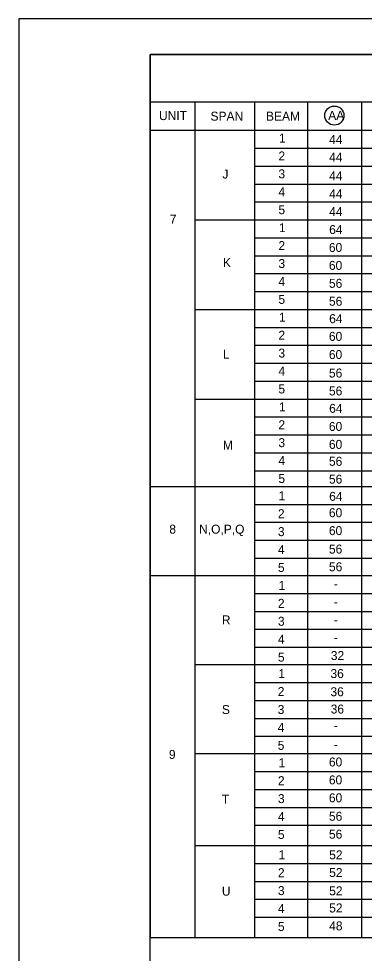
# Model space of a CAD drawing. Extents: x -50.5 to -14.4, y -5.1 to 16.9.
# Drawn here: x -50.52 to -45.7, y 3.9 to 16.93 of the extents above; entities that cross this region are included whole.
import ezdxf

# ---------------------------------------------------------------- set-up
doc = ezdxf.new("R2010")
doc.units = 0
for name, color, linetype in [('BR_AUTO DIMENSION', 7, 'Continuous'), ('BR_BORDER LINES', 7, 'Continuous'), ('BR_TABLE LINES', 7, 'Continuous'), ('BR_TEXT', 7, 'Continuous'), ('Level 31', 7, 'Continuous')]:
    doc.layers.add(name, color=color, linetype=linetype)

msp = doc.modelspace()

# ---------------------------------------------------------------- linework, layer by layer
at = {"layer": 'BR_AUTO DIMENSION'}
msp.add_circle((-46.121, 15.583), 0.133, dxfattribs=at)
at = {"layer": 'BR_BORDER LINES'}
for p, q in [((-48.685, 16.434), (-48.685, 4.12)), ((-48.685, 16.434), (-37.494, 16.434)), ((-15.019, 16.434), (-48.685, 16.434)), ((-48.685, -4.566), (-48.685, 16.434)), ((-48.685, 4.12), (-37.494, 4.12))]:
    msp.add_line(p, q, dxfattribs=at)
at = {"layer": 'BR_TABLE LINES'}
for p, q in [((-48.685, 15.775), (-37.494, 15.775)), ((-48.065, 15.775), (-48.065, 4.12)), ((-47.233, 15.775), (-47.233, 4.12)), ((-46.494, 15.775), (-46.494, 4.12)), ((-46.494, 15.775), (-46.494, 4.12)), ((-45.744, 15.775), (-45.744, 4.12)), ((-48.685, 15.378), (-37.494, 15.378)), ((-47.233, 15.128), (-37.494, 15.128)), ((-47.233, 14.878), (-37.494, 14.878)), ((-47.233, 14.628), (-37.494, 14.628)), ((-47.233, 14.378), (-37.494, 14.378)), ((-48.065, 14.129), (-37.494, 14.129)), ((-47.233, 13.879), (-37.494, 13.879)), ((-47.233, 13.629), (-37.494, 13.629)), ((-47.233, 13.379), (-37.494, 13.379)), ((-47.233, 13.129), (-37.494, 13.129)), ((-48.065, 12.879), (-37.494, 12.879)), ((-47.233, 12.629), (-37.494, 12.629)), ((-47.233, 12.379), (-37.494, 12.379)), ((-47.233, 12.129), (-37.494, 12.129)), ((-47.233, 11.879), (-37.494, 11.879)), ((-48.065, 11.63), (-37.494, 11.63)), ((-47.233, 11.38), (-37.494, 11.38)), ((-47.233, 11.13), (-37.494, 11.13)), ((-47.233, 10.88), (-37.494, 10.88)), ((-47.233, 10.63), (-37.494, 10.63)), ((-48.685, 10.411), (-37.494, 10.411)), ((-47.233, 10.161), (-37.494, 10.161)), ((-47.233, 9.911), (-37.494, 9.911)), ((-47.233, 9.661), (-37.494, 9.661)), ((-47.233, 9.411), (-37.494, 9.411)), ((-48.685, 9.169), (-37.494, 9.169)), ((-47.233, 8.919), (-37.494, 8.919)), ((-47.233, 8.669), (-37.494, 8.669)), ((-47.233, 8.419), (-37.494, 8.419)), ((-47.233, 8.169), (-37.494, 8.169)), ((-48.065, 7.927), (-37.494, 7.927)), ((-47.233, 7.677), (-37.494, 7.677)), ((-47.233, 7.427), (-37.494, 7.427)), ((-47.233, 7.177), (-37.494, 7.177)), ((-47.233, 6.927), (-37.494, 6.927)), ((-48.065, 6.685), (-37.494, 6.685)), ((-47.233, 6.435), (-37.494, 6.435)), ((-47.233, 6.185), (-37.494, 6.185)), ((-47.233, 5.935), (-37.494, 5.935)), ((-47.233, 5.685), (-37.494, 5.685)), ((-48.065, 5.403), (-37.494, 5.403)), ((-47.233, 5.153), (-37.494, 5.153)), ((-47.233, 4.903), (-37.494, 4.903)), ((-47.233, 4.653), (-37.494, 4.653)), ((-47.233, 4.403), (-37.494, 4.403))]:
    msp.add_line(p, q, dxfattribs=at)
at = {"layer": 'Level 31'}
msp.add_lwpolyline([(-50.519, -5.066), (-14.519, -5.066), (-14.519, 16.934), (-50.519, 16.934)], close=True, dxfattribs=at)

# ---------------------------------------------------------------- texts
at = {"layer": 'BR_TEXT'}
for s, p in [('UNIT', (-48.564, 15.52)), ('AA', (-46.206, 15.523)), ('SPAN', (-47.846, 15.512)), ('BEAM', (-47.073, 15.512)), ('J', (-47.68, 14.705)), ('7', (-48.413, 14.076)), ('K', (-47.674, 13.47)), ('L', (-47.674, 12.192)), ('M', (-47.674, 10.922)), ('8', (-48.42, 9.753)), ('N,O,P,Q', (-48.005, 9.752)), ('R', (-47.688, 8.487)), ('S', (-47.688, 7.237)), ('9', (-48.426, 6.611)), ('T', (-47.688, 5.987)), ('U', (-47.688, 4.704))]:
    msp.add_text(s, height=0.125, rotation=360, dxfattribs=at).set_placement(p)
for s, p in [('1', (-46.892, 15.207)), ('44', (-46.193, 15.188)), ('2', (-46.9, 14.957)), ('44', (-46.193, 14.941)), ('3', (-46.9, 14.707)), ('44', (-46.193, 14.68)), ('4', (-46.9, 14.457)), ('44', (-46.193, 14.43)), ('5', (-46.9, 14.207)), ('44', (-46.193, 14.181)), ('1', (-46.892, 13.957)), ('64', (-46.193, 13.931)), ('2', (-46.9, 13.707)), ('60', (-46.197, 13.681)), ('3', (-46.9, 13.457)), ('60', (-46.197, 13.431)), ('4', (-46.9, 13.207)), ('56', (-46.196, 13.181)), ('5', (-46.9, 12.957)), ('56', (-46.196, 12.931)), ('1', (-46.892, 12.708)), ('64', (-46.193, 12.688)), ('2', (-46.9, 12.458)), ('60', (-46.197, 12.441)), ('3', (-46.9, 12.208)), ('60', (-46.197, 12.188)), ('4', (-46.9, 11.958)), ('56', (-46.196, 11.93)), ('5', (-46.9, 11.708)), ('56', (-46.196, 11.68)), ('1', (-46.892, 11.459)), ('64', (-46.193, 11.437)), ('2', (-46.9, 11.209)), ('60', (-46.197, 11.185)), ('3', (-46.9, 10.959)), ('60', (-46.197, 10.935)), ('4', (-46.9, 10.709)), ('56', (-46.196, 10.699)), ('5', (-46.9, 10.459)), ('56', (-46.196, 10.45)), ('1', (-46.899, 10.218)), ('64', (-46.193, 10.21)), ('2', (-46.907, 9.968)), ('60', (-46.197, 9.982)), ('3', (-46.907, 9.718)), ('60', (-46.197, 9.732)), ('4', (-46.907, 9.468)), ('56', (-46.196, 9.475)), ('5', (-46.907, 9.218)), ('56', (-46.196, 9.228)), ('1', (-46.899, 8.968)), ('-', (-46.128, 8.99)), ('2', (-46.907, 8.718)), ('-', (-46.128, 8.74)), ('3', (-46.907, 8.468)), ('-', (-46.128, 8.49)), ('4', (-46.907, 8.218)), ('-', (-46.128, 8.24)), ('5', (-46.907, 7.968)), ('32', (-46.17, 7.99)), ('1', (-46.901, 7.738)), ('36', (-46.175, 7.739)), ('2', (-46.91, 7.488)), ('36', (-46.175, 7.485)), ('3', (-46.91, 7.238)), ('36', (-46.172, 7.244)), ('4', (-46.91, 6.988)), ('-', (-46.128, 7.013)), ('5', (-46.91, 6.738)), ('-', (-46.128, 6.748)), ('1', (-46.899, 6.495)), ('60', (-46.197, 6.506)), ('2', (-46.907, 6.245)), ('60', (-46.197, 6.256)), ('60', (-46.197, 6.006)), ('3', (-46.907, 5.995)), ('4', (-46.907, 5.745)), ('56', (-46.196, 5.749)), ('5', (-46.907, 5.495)), ('56', (-46.196, 5.499)), ('1', (-46.899, 5.212)), ('52', (-46.193, 5.211)), ('2', (-46.907, 4.962)), ('52', (-46.193, 4.964)), ('3', (-46.907, 4.712)), ('52', (-46.193, 4.709)), ('4', (-46.907, 4.462)), ('52', (-46.193, 4.47)), ('5', (-46.907, 4.212)), ('48', (-46.193, 4.22))]:
    msp.add_text(s, height=0.125, dxfattribs=at).set_placement(p)

doc.saveas('drawing.dxf')
